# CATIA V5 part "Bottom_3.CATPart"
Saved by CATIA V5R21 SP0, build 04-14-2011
Part number: Part1.4
Material "Fire Red": density 7860 kg/m3, Young's modulus 2e+11 Pa, Poisson ratio 0.266
Bounding box of the stored display mesh (mm): x 0 to 45, y -21.5 to 21.5, z -21.5 to 21.5
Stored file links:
  C:\Users\RIAD MAHAMUD PIASH\Desktop\Project\Bottom_3.CATPart
  C:\Program Files (x86)\Dassault Systemes\B21\intel_a\startup\materials\Catalog.CATMaterial
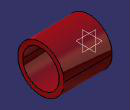
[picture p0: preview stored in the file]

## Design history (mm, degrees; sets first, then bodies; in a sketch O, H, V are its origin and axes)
Body1 (main body), material "Fire Red"
  Sketch1 on yz-plane, origin (0, 0, 0), H (0, 1, 0), V (0, 0, 1)
    circle A1 centre (0, 0) radius 21.5
    circle A2 centre (0, 0) radius 17
    radius A2 = 17
    radius A1 = 21.5
  Pad1: profile Sketch1, direction (1, 0, 0), length 45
